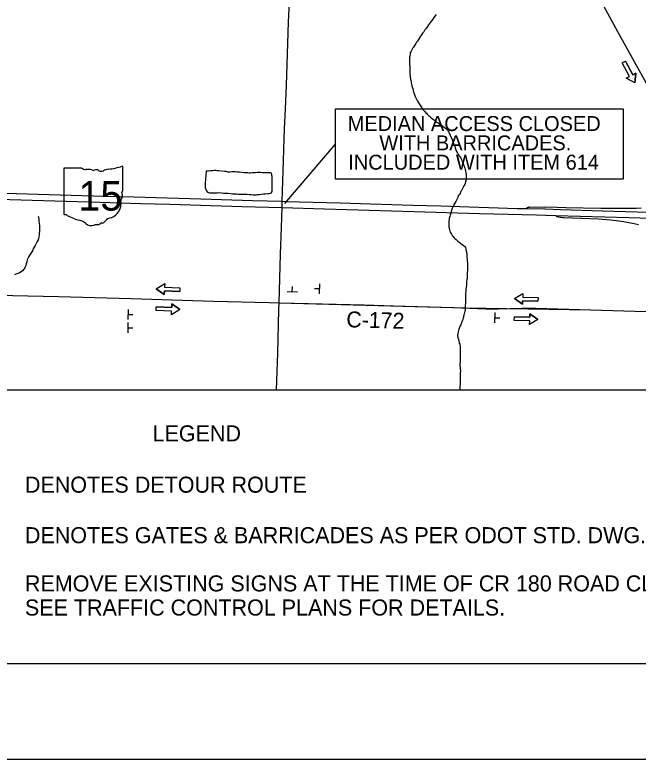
# Model space of a CAD drawing. Extents: x 1 to 1675, y -2 to 1113.
# Drawn here: x 1659.58 to 1669.35, y 1080.02 to 1091.69 of the extents above; entities that cross this region are included whole.
import ezdxf

# ---------------------------------------------------------------- set-up
doc = ezdxf.new("R2010")
doc.units = 0
for name, color, linetype in [('GM_X_County_Road_Text', 7, 'Continuous'), ('GM_X_Interchange_Ramps', 7, 'Continuous'), ('GM_X_State_Route', 7, 'Continuous'), ('GM_X_State_Shield', 7, 'Continuous'), ('SC_Scratch1', 7, 'Continuous'), ('SH_Border', 7, 'Continuous'), ('SH_Cut_Line', 7, 'Continuous'), ('SH_Data', 7, 'Continuous'), ('SH_Text', 7, 'Continuous'), ('SN_P_Signs', 7, 'Continuous')]:
    doc.layers.add(name, color=color, linetype=linetype)

msp = doc.modelspace()

# ---------------------------------------------------------------- linework, layer by layer
at = {"layer": 'GM_X_Interchange_Ramps'}
for points in [[(1667.876, 1088.666), (1667.653, 1088.669), (1667.647, 1088.669), (1667.642, 1088.668), (1667.637, 1088.668), (1667.631, 1088.667), (1667.624, 1088.665), (1667.62, 1088.663), (1667.617, 1088.662), (1667.612, 1088.66), (1667.608, 1088.657), (1667.603, 1088.653), (1667.6, 1088.649)], [(1669.4, 1088.655), (1669.322, 1088.65), (1669.143, 1088.649), (1668.764, 1088.651), (1668.216, 1088.661), (1668.076, 1088.664), (1667.653, 1088.669), (1667.647, 1088.669), (1667.642, 1088.668), (1667.637, 1088.668), (1667.631, 1088.667), (1667.624, 1088.665), (1667.62, 1088.663), (1667.617, 1088.662), (1667.612, 1088.66), (1667.608, 1088.657), (1667.603, 1088.653), (1667.6, 1088.649)], [(1668.061, 1088.538), (1668.066, 1088.532), (1668.071, 1088.529), (1668.076, 1088.525), (1668.086, 1088.523), (1668.102, 1088.52), (1668.132, 1088.515), (1668.146, 1088.514), (1668.168, 1088.511), (1668.187, 1088.51), (1668.728, 1088.49), (1668.919, 1088.473), (1669.046, 1088.459), (1669.126, 1088.447), (1669.206, 1088.433), (1669.29, 1088.417), (1669.356, 1088.401)]]:
    msp.add_lwpolyline(points, dxfattribs=at)
at = {"layer": 'GM_X_State_Route'}
for points in [[(1653.176, 1089.072), (1653.709, 1089.056), (1654.406, 1089.036), (1654.889, 1089.02), (1655.371, 1089.008), (1656.266, 1088.983), (1656.654, 1088.971), (1657.534, 1088.945), (1659.61, 1088.884), (1660.288, 1088.866), (1660.813, 1088.849), (1661.447, 1088.831), (1662.496, 1088.801), (1663.305, 1088.777), (1663.771, 1088.764), (1663.829, 1088.762), (1664.682, 1088.737), (1665.163, 1088.724), (1665.819, 1088.704), (1666.256, 1088.69), (1667.456, 1088.651), (1667.6, 1088.649), (1667.876, 1088.644)], [(1653.176, 1088.972), (1654.106, 1088.945), (1655.155, 1088.914), (1655.854, 1088.894), (1656.649, 1088.869), (1657.244, 1088.851), (1657.682, 1088.839), (1658.51, 1088.819), (1659.319, 1088.795), (1660.916, 1088.748), (1661.55, 1088.729), (1662.009, 1088.718), (1663.147, 1088.683), (1663.769, 1088.665), (1664.437, 1088.645), (1665.837, 1088.604), (1666.865, 1088.573), (1667.758, 1088.549), (1667.876, 1088.545)], [(1653.176, 1088.972), (1654.106, 1088.945), (1655.155, 1088.914), (1655.854, 1088.894), (1656.649, 1088.869), (1657.244, 1088.851), (1657.682, 1088.839), (1658.51, 1088.819), (1659.319, 1088.795), (1660.916, 1088.748), (1661.55, 1088.729), (1662.009, 1088.718), (1663.147, 1088.683), (1663.769, 1088.665), (1664.437, 1088.645), (1665.837, 1088.604), (1666.865, 1088.573), (1667.758, 1088.549), (1668.061, 1088.538), (1669.205, 1088.508), (1669.555, 1088.5), (1670.189, 1088.48), (1670.462, 1088.472)], [(1657.534, 1088.945), (1659.61, 1088.884), (1660.288, 1088.866), (1660.813, 1088.849), (1661.447, 1088.831), (1662.496, 1088.801), (1663.305, 1088.777), (1663.771, 1088.764), (1663.829, 1088.762), (1664.682, 1088.737), (1665.163, 1088.724), (1665.819, 1088.704), (1666.256, 1088.69), (1667.456, 1088.651), (1667.6, 1088.649), (1667.895, 1088.643), (1668.137, 1088.634), (1668.791, 1088.614), (1669.512, 1088.593), (1670.466, 1088.566), (1670.98, 1088.551), (1672.202, 1088.516)]]:
    msp.add_lwpolyline(points, dxfattribs=at)
at = {"layer": 'GM_X_State_Shield'}
for p, q in [((1660.348, 1089.272), (1660.348, 1088.568)), ((1660.629, 1089.284), (1660.357, 1089.284)), ((1661.276, 1088.933), (1661.276, 1089.302)), ((1661.276, 1088.933), (1661.276, 1088.933))]:
    msp.add_line(p, q, dxfattribs=at)
for centre, radius, start, end in [((1660.358, 1089.274), 0.0108, 98.1301, 188.1301), ((1660.693, 1089.366), 0.104, 231.6195, 271.1119), ((1660.728, 1088.889), 0.374, 80.4867, 94.9883), ((1661.071, 1089.069), 0.198, 97.3462, 120.7689), ((1660.945, 1090.245), 0.984, 275.8445, 288.9065), ((1661.266, 1089.303), 0.0103, 351.8621, 97.738), ((1660.813, 1089.277), 0.0301, 219.7921, 297.1024), ((1660.857, 1089.196), 0.0626, 54.4667, 119.1411), ((1660.938, 1089.308), 0.0753, 233.8562, 294.8282), ((1661.273, 1088.906), 0.016, 107.944, 210.337), ((1661.265, 1088.932), 0.0111, 289.6038, 7.7341), ((1661.313, 1088.779), 0.0698, 136.8065, 186.9296), ((1661.172, 1088.86), 0.096, 340.033, 23.6496), ((1661, 1088.732), 0.246, 292.3089, 8.9858), ((1660.359, 1088.566), 0.0108, 171.9584, 258.3066), ((1660.36, 1088.638), 0.0828, 267.339, 280.6039), ((1660.377, 1088.527), 0.0298, 29.7484, 93.2717), ((1660.754, 1089.16), 0.711, 240.4129, 257.1985), ((1660.542, 1088.251), 0.222, 47.1842, 75.836), ((1660.933, 1088.499), 0.0795, 282.8732, 323.2771), ((1661.104, 1088.37), 0.135, 94.4031, 142.5768), ((1660.783, 1088.524), 0.141, 230.7004, 286.2918), ((1660.864, 1088.28), 0.116, 85.6951, 111.2099), ((1660.874, 1088.471), 0.0752, 268.777, 315.5493), ((1660.942, 1088.403), 0.0212, 65.7517, 132.6484)]:
    msp.add_arc(centre, radius, start, end, dxfattribs=at)
at = {"layer": 'SC_Scratch1'}
for points in [[(1666.183, 1091.694), (1666.167, 1091.67), (1666.151, 1091.646), (1666.132, 1091.617), (1666.113, 1091.59), (1666.097, 1091.569)], [(1666.097, 1091.569), (1666.081, 1091.55), (1666.065, 1091.529), (1666.049, 1091.505), (1666.03, 1091.473), (1666.006, 1091.449), (1665.99, 1091.422), (1665.971, 1091.398), (1665.955, 1091.371), (1665.939, 1091.35), (1665.925, 1091.326), (1665.907, 1091.299), (1665.893, 1091.275), (1665.877, 1091.257), (1665.866, 1091.238), (1665.855, 1091.219), (1665.839, 1091.195), (1665.831, 1091.182), (1665.821, 1091.169), (1665.796, 1091.129), (1665.788, 1091.107), (1665.78, 1091.091), (1665.778, 1091.078), (1665.775, 1091.064), (1665.772, 1091.04), (1665.769, 1091.024), (1665.769, 1091.011), (1665.769, 1090.995), (1665.769, 1090.979), (1665.769, 1090.963), (1665.769, 1090.941), (1665.769, 1090.923), (1665.769, 1090.901), (1665.772, 1090.877), (1665.772, 1090.858), (1665.772, 1090.834), (1665.772, 1090.808), (1665.772, 1090.783), (1665.772, 1090.765), (1665.774, 1090.751), (1665.777, 1090.738), (1665.777, 1090.725), (1665.779, 1090.706), (1665.782, 1090.692), (1665.785, 1090.671), (1665.79, 1090.655), (1665.793, 1090.636), (1665.795, 1090.618), (1665.798, 1090.601), (1665.803, 1090.588), (1665.806, 1090.572), (1665.811, 1090.556), (1665.814, 1090.54), (1665.822, 1090.516), (1665.824, 1090.502), (1665.83, 1090.481), (1665.835, 1090.465), (1665.84, 1090.451), (1665.843, 1090.435), (1665.851, 1090.422), (1665.854, 1090.406), (1665.862, 1090.393), (1665.87, 1090.374), (1665.88, 1090.352), (1665.891, 1090.334), (1665.92, 1090.291), (1665.931, 1090.275), (1665.942, 1090.259), (1665.95, 1090.242), (1665.96, 1090.229), (1665.968, 1090.216), (1665.976, 1090.202), (1665.99, 1090.189), (1666.006, 1090.173), (1666.019, 1090.157), (1666.032, 1090.143), (1666.046, 1090.13), (1666.067, 1090.108), (1666.08, 1090.098), (1666.094, 1090.081), (1666.107, 1090.073), (1666.128, 1090.055), (1666.144, 1090.044), (1666.158, 1090.033), (1666.177, 1090.02), (1666.193, 1090.006), (1666.214, 1089.993), (1666.233, 1089.979), (1666.249, 1089.969), (1666.267, 1089.958), (1666.291, 1089.942), (1666.31, 1089.926), (1666.331, 1089.909), (1666.345, 1089.899), (1666.358, 1089.885), (1666.369, 1089.872), (1666.377, 1089.858), (1666.382, 1089.845), (1666.39, 1089.832), (1666.395, 1089.818), (1666.403, 1089.8)], [(1666.403, 1089.8), (1666.409, 1089.781), (1666.419, 1089.767), (1666.427, 1089.749), (1666.435, 1089.73), (1666.443, 1089.711), (1666.467, 1089.65), (1666.475, 1089.628), (1666.483, 1089.601), (1666.491, 1089.572), (1666.502, 1089.545), (1666.518, 1089.516), (1666.531, 1089.497), (1666.542, 1089.483), (1666.553, 1089.47), (1666.561, 1089.457), (1666.569, 1089.443), (1666.577, 1089.43), (1666.587, 1089.408), (1666.595, 1089.387), (1666.606, 1089.36), (1666.616, 1089.336), (1666.622, 1089.312), (1666.63, 1089.293), (1666.632, 1089.28), (1666.638, 1089.264), (1666.643, 1089.245), (1666.646, 1089.229), (1666.651, 1089.21), (1666.654, 1089.194), (1666.656, 1089.178), (1666.656, 1089.162), (1666.656, 1089.141), (1666.656, 1089.125), (1666.653, 1089.098), (1666.651, 1089.084), (1666.645, 1089.066), (1666.64, 1089.044), (1666.632, 1089.026), (1666.621, 1089.004), (1666.61, 1088.983), (1666.597, 1088.961), (1666.586, 1088.943), (1666.578, 1088.924), (1666.567, 1088.911), (1666.559, 1088.887), (1666.543, 1088.865), (1666.532, 1088.847), (1666.522, 1088.823), (1666.508, 1088.791), (1666.492, 1088.761), (1666.476, 1088.732), (1666.462, 1088.705), (1666.452, 1088.681), (1666.441, 1088.66), (1666.433, 1088.638), (1666.409, 1088.563), (1666.403, 1088.545), (1666.398, 1088.523), (1666.392, 1088.507), (1666.39, 1088.491), (1666.387, 1088.475), (1666.384, 1088.454), (1666.382, 1088.43), (1666.382, 1088.408), (1666.381, 1088.384), (1666.384, 1088.36), (1666.387, 1088.336), (1666.392, 1088.317), (1666.397, 1088.299), (1666.405, 1088.277), (1666.416, 1088.261), (1666.427, 1088.245), (1666.437, 1088.229), (1666.451, 1088.213), (1666.464, 1088.197), (1666.48, 1088.181), (1666.501, 1088.165), (1666.525, 1088.14), (1666.544, 1088.124), (1666.568, 1088.105), (1666.595, 1088.084), (1666.616, 1088.068), (1666.63, 1088.057), (1666.643, 1088.038), (1666.648, 1088.017), (1666.651, 1088.004), (1666.653, 1087.987), (1666.659, 1087.969), (1666.661, 1087.955), (1666.664, 1087.942), (1666.664, 1087.923), (1666.664, 1087.904), (1666.667, 1087.88), (1666.669, 1087.854), (1666.672, 1087.83), (1666.674, 1087.797), (1666.674, 1087.776), (1666.674, 1087.749), (1666.674, 1087.725), (1666.674, 1087.696)], [(1662.581, 1089.237), (1662.565, 1089.047), (1662.565, 1089.004), (1662.567, 1088.977), (1662.572, 1088.964), (1662.575, 1088.948), (1662.583, 1088.926), (1662.602, 1088.905), (1662.634, 1088.897), (1662.658, 1088.894), (1662.671, 1088.894), (1662.687, 1088.894), (1662.706, 1088.894), (1662.725, 1088.894), (1662.752, 1088.896), (1662.781, 1088.899), (1662.819, 1088.896), (1662.851, 1088.893), (1662.885, 1088.893), (1662.923, 1088.888), (1662.96, 1088.885), (1662.995, 1088.882), (1663.027, 1088.879), (1663.057, 1088.879), (1663.086, 1088.876), (1663.113, 1088.876), (1663.142, 1088.876), (1663.185, 1088.876), (1663.22, 1088.873), (1663.255, 1088.868), (1663.287, 1088.868), (1663.316, 1088.865), (1663.343, 1088.865), (1663.367, 1088.865), (1663.388, 1088.867), (1663.415, 1088.87), (1663.445, 1088.873), (1663.477, 1088.878), (1663.506, 1088.88), (1663.546, 1088.883), (1663.57, 1088.886), (1663.589, 1088.891), (1663.605, 1088.899), (1663.613, 1088.918), (1663.613, 1088.931), (1663.616, 1088.952), (1663.616, 1088.998), (1663.616, 1089.014), (1663.616, 1089.033), (1663.616, 1089.049)], [(1663.616, 1089.049), (1663.616, 1089.067), (1663.616, 1089.083), (1663.614, 1089.107), (1663.614, 1089.129), (1663.614, 1089.15), (1663.611, 1089.166), (1663.609, 1089.18), (1663.603, 1089.204), (1663.587, 1089.207), (1663.574, 1089.207), (1663.555, 1089.207), (1663.536, 1089.207), (1663.52, 1089.207), (1663.504, 1089.21), (1663.485, 1089.21), (1663.464, 1089.21), (1663.432, 1089.212), (1663.403, 1089.213), (1663.378, 1089.213), (1663.354, 1089.21), (1663.328, 1089.207), (1663.304, 1089.207), (1663.277, 1089.205), (1663.255, 1089.205), (1663.231, 1089.208), (1663.202, 1089.21), (1663.172, 1089.211), (1663.132, 1089.213), (1663.103, 1089.219), (1663.071, 1089.222), (1663.041, 1089.224), (1663.012, 1089.224), (1662.98, 1089.225), (1662.95, 1089.222), (1662.921, 1089.222), (1662.892, 1089.228), (1662.865, 1089.23), (1662.779, 1089.239), (1662.752, 1089.241), (1662.731, 1089.244), (1662.704, 1089.244), (1662.677, 1089.242), (1662.651, 1089.239), (1662.629, 1089.236), (1662.611, 1089.239), (1662.597, 1089.236), (1662.587, 1089.237), (1662.581, 1089.237)], [(1659.949, 1088.531), (1659.952, 1088.515), (1659.957, 1088.48), (1659.96, 1088.445), (1659.965, 1088.413), (1659.97, 1088.386), (1659.97, 1088.357), (1659.97, 1088.325), (1659.967, 1088.292), (1659.965, 1088.263), (1659.962, 1088.236), (1659.959, 1088.207), (1659.951, 1088.177), (1659.946, 1088.161), (1659.932, 1088.132), (1659.922, 1088.111), (1659.911, 1088.089), (1659.9, 1088.068), (1659.884, 1088.044), (1659.87, 1088.02), (1659.857, 1087.985), (1659.836, 1087.956), (1659.819, 1087.926), (1659.801, 1087.897), (1659.787, 1087.868), (1659.776, 1087.844), (1659.768, 1087.814), (1659.758, 1087.782), (1659.752, 1087.755), (1659.741, 1087.734), (1659.736, 1087.721), (1659.723, 1087.699), (1659.701, 1087.675), (1659.68, 1087.657), (1659.653, 1087.643), (1659.626, 1087.63), (1659.599, 1087.619), (1659.575, 1087.611)], [(1666.674, 1087.696), (1666.671, 1087.629), (1666.671, 1087.61), (1666.671, 1087.589), (1666.669, 1087.565), (1666.666, 1087.535), (1666.663, 1087.508), (1666.66, 1087.476), (1666.658, 1087.444), (1666.655, 1087.415), (1666.652, 1087.391), (1666.649, 1087.367), (1666.649, 1087.343), (1666.647, 1087.321), (1666.647, 1087.297), (1666.644, 1087.278), (1666.644, 1087.254), (1666.644, 1087.22), (1666.644, 1087.19), (1666.644, 1087.163), (1666.641, 1087.139), (1666.641, 1087.118), (1666.641, 1087.097), (1666.641, 1087.08), (1666.638, 1087.067), (1666.638, 1087.054), (1666.633, 1087.038), (1666.63, 1087.022), (1666.624, 1087), (1666.619, 1086.976), (1666.616, 1086.96), (1666.614, 1086.947), (1666.608, 1086.928), (1666.603, 1086.912), (1666.597, 1086.899), (1666.592, 1086.885), (1666.584, 1086.864), (1666.576, 1086.84), (1666.573, 1086.827), (1666.562, 1086.808), (1666.552, 1086.786), (1666.546, 1086.773), (1666.538, 1086.757), (1666.522, 1086.696), (1666.522, 1086.677), (1666.519, 1086.658), (1666.525, 1086.634), (1666.527, 1086.618), (1666.533, 1086.605), (1666.535, 1086.589), (1666.541, 1086.575), (1666.546, 1086.554), (1666.548, 1086.538), (1666.554, 1086.522), (1666.556, 1086.508), (1666.559, 1086.484), (1666.559, 1086.471), (1666.559, 1086.457), (1666.562, 1086.439), (1666.562, 1086.415), (1666.561, 1086.361), (1666.559, 1086.318), (1666.559, 1086.283), (1666.559, 1086.249), (1666.558, 1086.217), (1666.558, 1086.19), (1666.561, 1086.163), (1666.561, 1086.134), (1666.564, 1086.107), (1666.563, 1086.072), (1666.563, 1086.045), (1666.563, 1086.011), (1666.563, 1085.978), (1666.563, 1085.944), (1666.56, 1085.914), (1666.56, 1085.89), (1666.558, 1085.866), (1666.558, 1085.839), (1666.555, 1085.813), (1666.554, 1085.801)]]:
    msp.add_lwpolyline(points, dxfattribs=at)
at = {"layer": 'SH_Border'}
msp.add_lwpolyline([(1651.439, 1081.517), (1673.939, 1081.517), (1673.939, 1111.517), (1651.439, 1111.517)], close=True, dxfattribs=at)
at = {"layer": 'SH_Cut_Line'}
msp.add_lwpolyline([(1649.939, 1080.017), (1675.439, 1080.017), (1675.439, 1113.017), (1649.939, 1113.017)], close=True, dxfattribs=at)
at = {"layer": 'SH_Data'}
msp.add_lwpolyline([(1653.176, 1105.401), (1672.202, 1105.401), (1672.202, 1085.801), (1653.176, 1085.801)], close=True, dxfattribs=at)
at = {"layer": 'SH_Text'}
for p, q in [((1669.102, 1090.932), (1669.153, 1090.959)), ((1669.216, 1090.719), (1669.102, 1090.932)), ((1669.267, 1090.746), (1669.153, 1090.959)), ((1669.165, 1090.692), (1669.216, 1090.719)), ((1669.3, 1090.619), (1669.165, 1090.692)), ((1669.315, 1090.772), (1669.267, 1090.746)), ((1669.3, 1090.619), (1669.315, 1090.772)), ((1663.813, 1088.726), (1664.609, 1089.659)), ((1661.799, 1087.393), (1661.93, 1087.473)), ((1661.93, 1087.473), (1661.928, 1087.416)), ((1661.928, 1087.416), (1662.17, 1087.408)), ((1662.17, 1087.408), (1662.168, 1087.35)), ((1661.799, 1087.393), (1661.924, 1087.304)), ((1661.924, 1087.304), (1661.926, 1087.358)), ((1661.926, 1087.358), (1662.168, 1087.35)), ((1667.412, 1087.238), (1667.543, 1087.318)), ((1667.543, 1087.318), (1667.541, 1087.261)), ((1663.724, 1087.17), (1666.635, 1087.091)), ((1667.412, 1087.238), (1667.537, 1087.149)), ((1667.537, 1087.149), (1667.539, 1087.203)), ((1667.539, 1087.203), (1667.781, 1087.195)), ((1667.541, 1087.261), (1667.783, 1087.253)), ((1667.783, 1087.253), (1667.781, 1087.195)), ((1661.797, 1087.05), (1661.799, 1087.108)), ((1662.039, 1087.042), (1661.797, 1087.05)), ((1662.04, 1087.1), (1661.799, 1087.108)), ((1662.167, 1087.065), (1662.037, 1086.985)), ((1662.042, 1087.154), (1662.04, 1087.1)), ((1662.167, 1087.065), (1662.042, 1087.154)), ((1666.635, 1087.091), (1668.605, 1087.062)), ((1668.605, 1087.062), (1669.301, 1087.042)), ((1662.037, 1086.985), (1662.039, 1087.042)), ((1667.41, 1086.895), (1667.412, 1086.953)), ((1667.653, 1086.945), (1667.412, 1086.953)), ((1667.655, 1086.999), (1667.653, 1086.945)), ((1667.78, 1086.91), (1667.655, 1086.999)), ((1669.301, 1087.042), (1669.979, 1087.023)), ((1667.652, 1086.887), (1667.41, 1086.895)), ((1667.78, 1086.91), (1667.65, 1086.83)), ((1667.65, 1086.83), (1667.652, 1086.887))]:
    msp.add_line(p, q, dxfattribs=at)
for points in [[(1667.033, 1094.982), (1667.036, 1094.978), (1667.342, 1094.472), (1667.512, 1094.191), (1667.558, 1094.114), (1667.634, 1093.983), (1667.856, 1093.58), (1667.972, 1093.37), (1668.278, 1092.813), (1668.487, 1092.428), (1668.665, 1092.099), (1668.747, 1091.947), (1669.028, 1091.427), (1669.209, 1091.095), (1669.731, 1090.153)], [(1656.567, 1087.364), (1656.593, 1087.363), (1657.042, 1087.348), (1657.533, 1087.339), (1659.064, 1087.298), (1660.268, 1087.27), (1661.405, 1087.238), (1662.695, 1087.198), (1663.57, 1087.174), (1663.724, 1087.17)]]:
    msp.add_lwpolyline(points, dxfattribs=at)
for points in [[(1669.153, 1090.959), (1669.267, 1090.746), (1669.315, 1090.772), (1669.3, 1090.619), (1669.165, 1090.692), (1669.216, 1090.719), (1669.102, 1090.932)], [(1664.609, 1090.215), (1669.117, 1090.215), (1669.117, 1089.112), (1664.609, 1089.112)], [(1662.168, 1087.35), (1661.926, 1087.358), (1661.924, 1087.304), (1661.799, 1087.393), (1661.93, 1087.473), (1661.928, 1087.416), (1662.17, 1087.408)], [(1667.781, 1087.195), (1667.539, 1087.203), (1667.537, 1087.149), (1667.412, 1087.238), (1667.543, 1087.318), (1667.541, 1087.261), (1667.783, 1087.253)], [(1661.799, 1087.108), (1662.04, 1087.1), (1662.042, 1087.154), (1662.167, 1087.065), (1662.037, 1086.985), (1662.039, 1087.042), (1661.797, 1087.05)], [(1667.412, 1086.953), (1667.653, 1086.945), (1667.655, 1086.999), (1667.78, 1086.91), (1667.65, 1086.83), (1667.652, 1086.887), (1667.41, 1086.895)]]:
    msp.add_lwpolyline(points, close=True, dxfattribs=at)
at = {"layer": 'SN_P_Signs'}
for p, q in [((1663.93, 1087.346), (1663.934, 1087.426)), ((1664.358, 1087.31), (1664.363, 1087.47)), ((1663.85, 1087.35), (1664.01, 1087.342)), ((1664.36, 1087.39), (1664.28, 1087.393)), ((1661.356, 1087.069), (1661.351, 1086.909)), ((1661.353, 1086.989), (1661.433, 1086.987)), ((1667.103, 1087.018), (1667.098, 1086.858)), ((1667.101, 1086.938), (1667.181, 1086.936)), ((1661.354, 1086.861), (1661.35, 1086.701)), ((1661.352, 1086.781), (1661.432, 1086.779))]:
    msp.add_line(p, q, dxfattribs=at)
for points in [[(1663.771, 1088.764), (1663.776, 1088.92), (1663.792, 1089.401), (1663.809, 1089.904), (1663.821, 1090.209), (1663.838, 1090.582), (1663.85, 1090.91), (1663.873, 1091.569), (1663.885, 1091.893), (1663.892, 1092.014), (1663.897, 1092.072), (1663.901, 1092.11), (1663.909, 1092.149), (1663.919, 1092.169), (1663.932, 1092.195), (1663.946, 1092.214), (1663.966, 1092.238)], [(1663.771, 1088.764), (1663.776, 1088.92), (1663.792, 1089.401), (1663.809, 1089.904), (1663.821, 1090.209), (1663.838, 1090.582), (1663.85, 1090.91), (1663.873, 1091.569), (1663.885, 1091.893), (1663.892, 1092.014), (1663.897, 1092.072), (1663.901, 1092.11), (1663.909, 1092.149), (1663.919, 1092.169), (1663.932, 1092.195), (1663.946, 1092.214), (1663.966, 1092.238)], [(1663.769, 1088.665), (1663.771, 1088.764)], [(1663.769, 1088.665), (1663.771, 1088.764)], [(1663.724, 1087.17), (1663.745, 1087.936), (1663.76, 1088.352), (1663.769, 1088.665)], [(1663.724, 1087.17), (1663.745, 1087.936), (1663.76, 1088.352), (1663.769, 1088.665)], [(1656.567, 1087.364), (1656.593, 1087.363), (1657.042, 1087.348), (1657.533, 1087.339), (1659.064, 1087.298), (1660.268, 1087.27), (1661.405, 1087.238), (1662.695, 1087.198), (1663.57, 1087.174), (1663.724, 1087.17)], [(1656.567, 1087.364), (1656.593, 1087.363), (1657.042, 1087.348), (1657.533, 1087.339), (1659.064, 1087.298), (1660.268, 1087.27), (1661.405, 1087.238), (1662.695, 1087.198), (1663.57, 1087.174), (1663.724, 1087.17)], [(1663.685, 1085.801), (1663.694, 1086.099), (1663.703, 1086.384), (1663.72, 1087.062), (1663.724, 1087.17)], [(1663.685, 1085.801), (1663.694, 1086.099), (1663.703, 1086.384), (1663.72, 1087.062), (1663.724, 1087.17)], [(1663.724, 1087.17), (1664.183, 1087.158), (1665.058, 1087.139), (1665.517, 1087.123), (1666.458, 1087.098), (1666.961, 1087.078), (1667.158, 1087.075), (1667.529, 1087.089), (1667.748, 1087.087), (1667.876, 1087.083)], [(1663.724, 1087.17), (1664.183, 1087.158), (1665.058, 1087.139), (1665.517, 1087.123), (1666.458, 1087.098), (1666.961, 1087.078), (1667.158, 1087.075), (1667.529, 1087.089), (1667.748, 1087.087), (1669.301, 1087.042), (1669.979, 1087.023), (1670.236, 1087.01), (1670.487, 1086.997), (1670.902, 1086.965)]]:
    msp.add_lwpolyline(points, dxfattribs=at)

# ---------------------------------------------------------------- texts
at = {"layer": 'GM_X_County_Road_Text'}
msp.add_text('C-172', height=0.25, rotation=358.3476, dxfattribs=at).set_placement((1664.774, 1086.789))
at = {"layer": 'GM_X_State_Shield'}
msp.add_text('15', height=0.4641, dxfattribs=at).set_placement((1660.577, 1088.617))
at = {"layer": 'SH_Text'}
for s, height, p in [('MEDIAN ACCESS CLOSED', 0.234, (1664.799, 1089.865)), ('WITH BARRICADES. ', 0.234, (1665.295, 1089.562)), ('INCLUDED WITH ITEM 614', 0.234, (1664.807, 1089.259)), ('LEGEND', 0.252, (1661.74, 1084.998)), ('DENOTES DETOUR ROUTE', 0.252, (1659.739, 1084.194)), ('DENOTES GATES & BARRICADES AS PER ODOT STD. DWG. MT-101.60', 0.252, (1659.739, 1083.402)), ('REMOVE EXISTING SIGNS AT THE TIME OF CR 180 ROAD CLOSURE.', 0.252, (1659.739, 1082.646)), ('SEE TRAFFIC CONTROL PLANS FOR DETAILS.', 0.252, (1659.739, 1082.268))]:
    msp.add_text(s, height=height, dxfattribs=at).set_placement(p)

doc.saveas('drawing.dxf')
